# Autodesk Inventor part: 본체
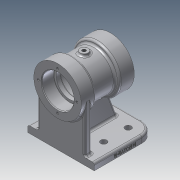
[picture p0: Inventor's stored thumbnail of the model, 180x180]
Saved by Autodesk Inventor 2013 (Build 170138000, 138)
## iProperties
Created: 2020-06
Part Number: 본체
Material: 알루미늄 6061
Document SubType Name: Modeling
Designer: 19
Density: 1 g/cm^3
Author: 19
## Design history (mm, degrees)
sketch "스케치17"
  geometry: C1 r 35 at (0, 0); 1 further point
  constraints: 1 centre point, 1 coincident
  dimensions: "d76" = 70 diameter of C1
extrude "돌출12" new body sketch "스케치17" distance "d77" = 22; taper "d78" = 0 deg
sketch "스케치18"
  geometry: C1 r 35 at (0, 0) reference; C2 r 29 at (0, 0)
  constraints: 1 centre point, 1 coincident
  dimensions: "d79" = 58 diameter of C2
extrude "돌출13" join sketch "스케치18" distance "d80" = 34; taper "d81" = 0 deg
sketch "스케치19"
  geometry: C1 r 29 at (0, 0) reference; C2 r 35 at (0, 0)
  constraints: 1 centre point, 1 coincident
  dimensions: "d82" = 70 diameter of C2
extrude "돌출14" join sketch "스케치19" distance "d83" = 22; taper "d84" = 0 deg
sketch "스케치20"
  geometry: C1 r 35 at (0, 0) reference; C2 r 23.5 at (0, 0)
  constraints: 1 centre point, 1 coincident
  dimensions: "d85" = 47 diameter of C2
extrude "돌출15" cut sketch "스케치20" distance "d86" = 18; taper "d87" = 0 deg
sketch "스케치21"
  geometry: C1 r 23.5 at (0, 0) reference; C2 r 20 at (0, 0)
  constraints: 1 centre point, 1 coincident
  dimensions: "d88" = 40 diameter of C2
extrude "돌출16" cut sketch "스케치21" distance "d89" = 6; taper "d90" = 0 deg
sketch "스케치22"
  geometry: C1 r 20 at (0, 0) reference; C2 r 23 at (0, 0)
  constraints: 1 centre point, 1 coincident
  dimensions: "d91" = 46 diameter of C2
extrude "돌출17" cut sketch "스케치22" distance "d92" = 30; taper "d93" = 0 deg
sketch "스케치23"
  geometry: C1 r 35 at (0, 0) reference; C2 r 23.5 at (0, 0)
  constraints: 1 centre point, 1 coincident
  dimensions: "d94" = 47 diameter of C2
extrude "돌출18" cut sketch "스케치23" distance "d95" = 18; taper "d96" = 0 deg
sketch "스케치24"
  geometry: C1 r 23.5 at (0, 0) reference; C2 r 20 at (0, 0)
  constraints: 1 centre point, 1 coincident
  dimensions: "d97" = 40 diameter of C2
extrude "돌출19" cut sketch "스케치24" distance "d98" = 6; taper "d99" = 0 deg
node "작업 평면4"
sketch "스케치25"
  geometry: L1 (-35, -78)-(35, -78) reference; L2 (-49, -73)-(49, -73); L3 (-49, -73)-(-49, 17); L4 (-49, 17)-(49, 17); L5 (49, 17)-(49, -73); 3 further points
  constraints: 8 end point, 3 perpendicular, 2 midpoint, 1 parallel, 1 vertical alignment
  dimensions: "d101" = 98 distance of L2.start L2.end; "d102" = 5 distance of point (0, -78) point (0, -73); "d103" = 90 distance of L2.start L3.end
extrude "돌출20" join sketch "스케치25" distance "d104" = 10; taper "d105" = 0 deg
sketch "스케치26"
  geometry: L1 (-73, 49)-(-73, -49) reference; L2 (-73, 35)-(-63, 35); L3 (-63, 35)-(-63, -35); L4 (-63, -35)-(-73, -35); L5 (-73, -35)-(-73, 35); 2 further points
  constraints: 8 end point, 2 midpoint, 2 parallel, 1 horizontal, 1 perpendicular
  dimensions: "d106" = 10 distance of L3.end L4.end; "d107" = 70 distance of L2.end L3.end
extrude "돌출21" join sketch "스케치26" stored distance "d108" = 10; taper "d109" = 0 deg
fillet "모깎기3" dims "d115" = 20
sketch "스케치28"
  geometry: A1 r 20 centre (-3, -29) between (-3, -49) and (17, -29) reference; A2 r 20 centre (-3, 29) between (17, 29) and (-3, 49) reference; 5 further points
  constraints: 2 coincident, 2 horizontal alignment, 1 vertical alignment
  dimensions: "d116" = 36 distance of point (-3, 29) point (-39, 29)
hole "구멍4" sketch "스케치28" at (-3, 29), (-3, -29), (-39, -29), (-39, 29) diameter "d118" = 9; stored, may be unused: countersink angle "d122" = 90 deg, drill point angle "d124" = 118 deg; dims "d119" = 10, "d120" = 4, "d121" = 2, "d123" = 12
sketch "스케치29" dims "d125" = 57
  geometry: C1 r 23.5 at (0, 0) reference; C2 r 35 at (0, 0) reference; 2 further points
  constraints: 2 vertical alignment, 1 coincident, 2 other
hole "구멍5" sketch "스케치29" at (0, 28.5) diameter "d126" = 3.242; stored, may be unused: countersink angle "d130" = 90 deg, drill point angle "d132" = 118 deg; dims "d127" = 10, "d128" = 4, "d129" = 2, "d131" = 12
node "작업 평면5"
sketch "스케치31"
  geometry: L1 (-35, -78)-(35, -78) reference; C1 r 6 at (0, -39); 2 further points
  constraints: 1 centre point, 1 midpoint, 1 vertical alignment
  dimensions: "d148" = 12 diameter of C1; "d149" = 39 distance of point (0, -78) C1.centre
extrude "돌출23" join sketch "스케치31" stored distance "d150" = 10; taper "d151" = 0 deg
sketch "스케치32"
  geometry: C1 r 6 at (0, 0) reference; 2 further points
  constraints: 1 coincident
hole "구멍7" sketch "스케치32" at (0, 0) diameter "d152" = 5.188; stored, may be unused: countersink angle "d156" = 90 deg, drill point angle "d158" = 0 deg; dims "d153" = 20, "d154" = 4, "d155" = 2, "d157" = 20
fillet "모깎기4" dims "d159" = 0.3
fillet "모깎기5" dims "d160" = 3
chamfer "모따기1" distance "d161" = 1; stored, may be unused: second distance "d162" = 2, angle "d163" = 45 deg
fillet "모깎기6" dims "d164" = 3
fillet "모깎기13" dims "d171" = 3
fillet "모깎기17" dims "d175" = 3
fillet "모깎기18" dims "d176" = 3
sketch "스케치33"
  geometry: L1 (0, 0)-(-7, 0) reference; L2 (0, 0)-(0, 70) reference; 2 further points
  constraints: 1 other
  dimensions: "d178" = 45 distance from line of L1 point (-4, 45); "d179" = 4 distance from line of L2 point (-4, 45)
feature "엠보싱1" sketch "스케치33" dims "d76" = 70, "d180" = 0.5, "d181" = 0
sketch "스케치35"
  geometry: L1 (-73, -5)-(5, -5); L2 (5, -5)-(5, 5); L3 (5, 5)-(-73, 5); L4 (-73, 5)-(-73, -5); L5 (-73, 49)-(-73, -49) reference; L6 (17, -29)-(17, 29) reference; 2 further points
  constraints: 8 end point, 2 midpoint, 2 parallel, 1 horizontal, 1 perpendicular
  dimensions: "d183" = 10 distance of L1.end L2.end; "d184" = 12 distance between parallel lines of L6 L2
extrude "돌출24" join sketch "스케치35" distance "d185" = 40; taper "d186" = 0 deg
feature "면 기울기3" dims angle "d187" = 20 deg
sketch "스케치36"
  geometry: L1 (-56, 5)-(-22, 5); L2 (-22, 5)-(-22, -5); L3 (-22, -5)-(-56, -5); L4 (-56, -5)-(-56, 5); 1 further point
  constraints: 8 end point, 2 parallel, 1 horizontal, 1 perpendicular
extrude "돌출25" join sketch "스케치36" stored distance "d188" = 40; taper "d189" = 0 deg
fillet "모깎기20" dims "d190" = 3
fillet "모깎기21" dims "d191" = 3
fillet "모깎기22" dims "d192" = 3
fillet "모깎기23" dims "d193" = 3
fillet "모깎기24" dims "d194" = 3
sketch "스케치37" dims "d195" = 57
  geometry: C1 r 35 at (0, 0) reference; C2 r 24.5 at (0, 0) reference; 2 further points
  constraints: 2 vertical alignment, 1 coincident, 2 other
hole "구멍8" sketch "스케치37" at (0, 28.5) diameter "d196" = 3.242; stored, may be unused: countersink angle "d200" = 90 deg, drill point angle "d202" = 118 deg; dims "d197" = 10, "d198" = 4, "d199" = 2, "d201" = 12
node "솔리드2"
pattern_circular "원형 패턴4" dims angle "d204" = 360 deg
pattern_circular "원형 패턴5" dims angle "d207" = 360 deg
other parameters: "d147" = -32
